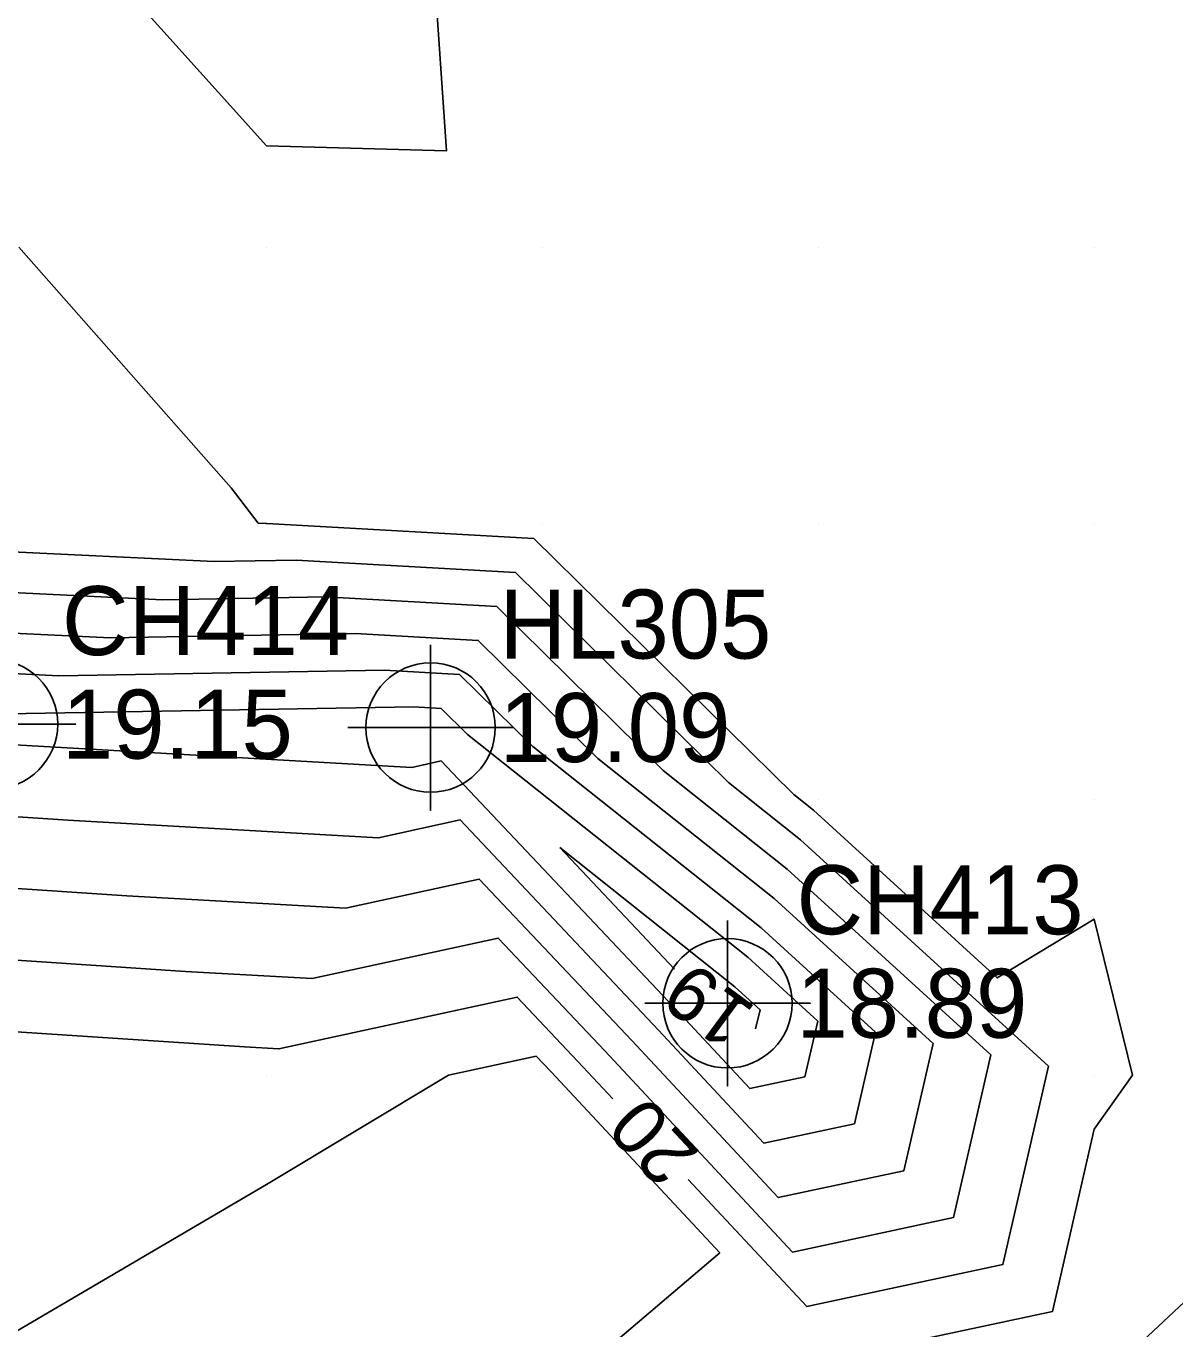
# Model space of a CAD drawing. Extents: x 2531902 to 2533249, y 715219 to 716099.
# Drawn here: x 2532801.29 to 2532842.92, y 715670.81 to 715718.01 of the extents above; entities that cross this region are included whole.
import ezdxf

# ---------------------------------------------------------------- set-up
doc = ezdxf.new("R2010")
doc.units = 0
for name, color, linetype in [('DTM Contours Major', 7, 'Continuous'), ('DTM Contours Major Text', 7, 'Continuous'), ('DTM Contours Minor', 7, 'Continuous'), ('Exist DTM QL2 LIDAR Elevation Point', 7, 'Continuous'), ('Exist DTM Regular Point CELL', 7, 'Continuous'), ('Exist DTM Regular Point Cogo Elevation', 7, 'Continuous'), ('Exist DTM Regular Point Cogo Number', 7, 'Continuous')]:
    doc.layers.add(name, color=color, linetype=linetype)

msp = doc.modelspace()

# ---------------------------------------------------------------- linework, layer by layer
at = {"layer": 'DTM Contours Major'}
for points in [[(2532838.339, 715680.326), (2532829.347, 715688.533), (2532826.742, 715690.602), (2532819.021, 715698.211), (2532811.077, 715698.659), (2532808.104, 715698.607), (2532800.012, 715698.999), (2532791.063, 715699.233), (2532791.151, 715690.31), (2532800.011, 715681.635), (2532809.202, 715681.024), (2532810.45, 715680.953), (2532819.089, 715682.829), (2532821.288, 715680.501), (2532822.549, 715679.15)], [(2532820.625, 715688.252), (2532826.975, 715683.209), (2532827.889, 715682.375), (2532827.728, 715681.676)], [(2532824.787, 715683.843), (2532820.625, 715688.252)], [(2532825.278, 715676.225), (2532829.577, 715671.62), (2532836.688, 715673.141), (2532838.339, 715680.326)]]:
    msp.add_lwpolyline(points, dxfattribs=at)
at = {"layer": 'DTM Contours Minor'}
for points in [[(2532804.306, 715720), (2532810, 715713.669), (2532816.518, 715713.482), (2532816.082, 715720)], [(2532800.412, 715670.412), (2532810, 715676.04), (2532816.6, 715680), (2532819.778, 715680.69), (2532820.314, 715680.122), (2532826.429, 715673.571), (2532822.24, 715670), (2532830, 715662.302), (2532832.673, 715667.327), (2532831.747, 715670), (2532838.481, 715671.44), (2532840, 715678.047), (2532841.386, 715680), (2532840, 715685.649), (2532836.476, 715683.524), (2532829.821, 715689.598), (2532829.107, 715690.165), (2532819.694, 715699.442), (2532810.011, 715699.987), (2532809.981, 715699.986), (2532809.699, 715700), (2532808.721, 715701.279), (2532801.023, 715710)], [(2532836.249, 715680.736), (2532828.872, 715687.468), (2532824.377, 715691.038), (2532818.347, 715696.981), (2532812.144, 715697.33), (2532806.226, 715697.228), (2532800.03, 715697.528), (2532793.177, 715697.707), (2532793.245, 715690.874), (2532800.029, 715684.231), (2532807.067, 715683.763), (2532811.654, 715683.503), (2532818.401, 715684.969), (2532822.261, 715680.879), (2532829.061, 715673.594), (2532834.895, 715674.842), (2532836.249, 715680.736)], [(2532834.159, 715681.145), (2532828.398, 715686.403), (2532822.012, 715691.475), (2532817.674, 715695.751), (2532813.21, 715696.002), (2532804.349, 715695.848), (2532800.048, 715696.057), (2532795.292, 715696.181), (2532795.338, 715691.439), (2532800.047, 715686.828), (2532804.932, 715686.503), (2532812.858, 715686.054), (2532817.712, 715687.108), (2532823.235, 715681.257), (2532828.545, 715675.568), (2532833.101, 715676.543), (2532834.159, 715681.145)], [(2532832.069, 715681.555), (2532827.924, 715685.339), (2532819.647, 715691.912), (2532817, 715694.52), (2532814.277, 715694.674), (2532802.471, 715694.469), (2532800.066, 715694.586), (2532797.406, 715694.655), (2532797.432, 715692.003), (2532800.065, 715689.424), (2532802.797, 715689.242), (2532814.062, 715688.604), (2532817.024, 715689.247), (2532824.209, 715681.636), (2532828.03, 715677.542), (2532831.308, 715678.243), (2532832.069, 715681.555)], [(2532829.979, 715681.965), (2532827.449, 715684.274), (2532817.282, 715692.348), (2532816.327, 715693.29), (2532815.343, 715693.345), (2532800.593, 715693.09), (2532800.084, 715693.115), (2532799.52, 715693.129), (2532799.525, 715692.567), (2532800.083, 715692.02), (2532800.663, 715691.982), (2532815.266, 715691.154), (2532816.335, 715691.386), (2532825.182, 715682.014), (2532827.514, 715679.516), (2532829.514, 715679.944), (2532829.979, 715681.965)], [(2532800.311, 715659.539), (2532809.625, 715658.849), (2532810.845, 715659.788), (2532810.839, 715668.249), (2532819.955, 715669.889), (2532820.053, 715669.863), (2532829.959, 715659.954), (2532838.836, 715659.611), (2532840.568, 715659.857), (2532840.598, 715660.088), (2532840.988, 715669.128), (2532841.385, 715670.029), (2532850.579, 715678.632)]]:
    msp.add_lwpolyline(points, dxfattribs=at)
at = {"layer": 'Exist DTM QL2 LIDAR Elevation Point'}
for p, q in [((2532810, 715710), (2532810, 715710)), ((2532820, 715710), (2532820, 715710)), ((2532830, 715710), (2532830, 715710)), ((2532840, 715710), (2532840, 715710)), ((2532810, 715700), (2532810, 715700)), ((2532820, 715700), (2532820, 715700)), ((2532830, 715700), (2532830, 715700)), ((2532840, 715700), (2532840, 715700)), ((2532830, 715690), (2532830, 715690)), ((2532840, 715690), (2532840, 715690)), ((2532810, 715680), (2532810, 715680)), ((2532820, 715680), (2532820, 715680)), ((2532840, 715680), (2532840, 715680))]:
    msp.add_line(p, q, dxfattribs=at)
at = {"layer": 'Exist DTM Regular Point CELL'}
for points in [[(2532800.088, 715695.719), (2532800.088, 715689.719), (2532800.088, 715692.719), (2532803.088, 715692.719), (2532797.088, 715692.719)], [(2532815.946, 715695.595), (2532815.946, 715689.595), (2532815.946, 715692.595), (2532818.946, 715692.595), (2532812.946, 715692.595)], [(2532826.707, 715685.607), (2532826.707, 715679.607), (2532826.707, 715682.607), (2532829.707, 715682.607), (2532823.707, 715682.607)]]:
    msp.add_lwpolyline(points, dxfattribs=at)
for centre in [(2532800.088, 715692.719), (2532815.946, 715692.595), (2532826.707, 715682.607)]:
    msp.add_circle(centre, 2.344, dxfattribs=at)

# ---------------------------------------------------------------- texts
at = {"layer": 'DTM Contours Major Text'}
for s, rotation, p in [('19', 143.6198, (2532827.799, 715682.423)), ('20', 133.0276, (2532825.757, 715677.178))]:
    msp.add_text(s, height=2, rotation=rotation, dxfattribs=at).set_placement(p)
at = {"layer": 'Exist DTM Regular Point Cogo Elevation'}
for s, p in [('19.15', (2532802.588, 715691.469)), ('19.09', (2532818.446, 715691.345)), ('18.89', (2532829.207, 715681.357))]:
    msp.add_text(s, height=2.5, dxfattribs=at).set_placement(p)
at = {"layer": 'Exist DTM Regular Point Cogo Number'}
for s, p in [('CH414', (2532802.588, 715695.219)), ('HL305', (2532818.446, 715695.095)), ('CH413', (2532829.207, 715685.107))]:
    msp.add_text(s, height=2.5, dxfattribs=at).set_placement(p)

doc.saveas('drawing.dxf')
